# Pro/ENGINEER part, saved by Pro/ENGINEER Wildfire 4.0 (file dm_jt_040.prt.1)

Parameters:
  METRIC = "NO"

Other parameters: PITCH, DRILL_POINT_ANGLE, DRILL_DEPTH, DRILL_DIAMETER, THREAD_DIAMETER, THREADS_PER_INCH, THREAD_DEPTH, THREAD_LENGTH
